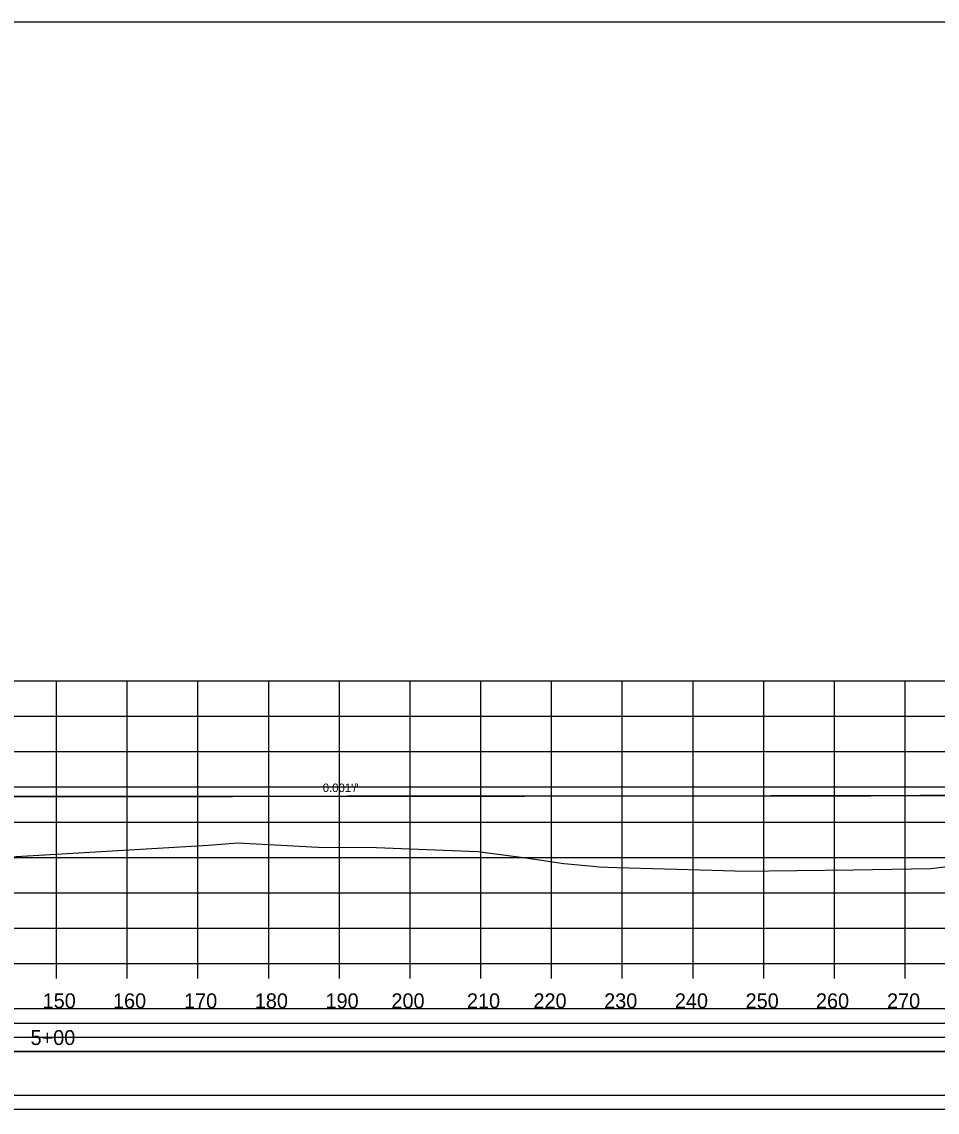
# Model space of a CAD drawing. Extents: x 1370565 to 1374448, y 301010 to 304637.
# Drawn here: x 1374196.6 to 1374326, y 301573 to 301727.1 of the extents above; entities that cross this region are included whole.
import ezdxf

# ---------------------------------------------------------------- set-up
doc = ezdxf.new("R2010")
doc.units = 0
for name, color, linetype in [('Default', 7, 'Continuous'), ('R_Axis', 7, 'Continuous'), ('R_Axis Annot', 7, 'Continuous'), ('R_Border', 7, 'Continuous'), ('R_Contours', 7, 'Continuous'), ('R_Drive', 7, 'Continuous'), ('R_Exist Surface', 7, 'Continuous'), ('R_Fin Surface', 7, 'Continuous'), ('R_Grid', 7, 'Continuous'), ('R_No Plot', 7, 'Continuous'), ('R_Xsect Slope', 7, 'Continuous')]:
    doc.layers.add(name, color=color, linetype=linetype)

msp = doc.modelspace()

# ---------------------------------------------------------------- linework, layer by layer
at = {"layer": 'Default'}
for points in [[(1373981.44, 301583.58), (1374421.61, 301583.58), (1374421.61, 301587.57), (1373981.44, 301587.57)], [(1373981.44, 301575.36), (1374421.61, 301575.36), (1374421.61, 301583.5), (1373981.44, 301583.5)]]:
    msp.add_lwpolyline(points, close=True, dxfattribs=at)
at = {"layer": 'R_Axis'}
for p, q in [((1373981.52, 301593.96), (1374421.52, 301593.96)), ((1374201.52, 301591.86), (1374201.52, 301593.96)), ((1374211.52, 301591.86), (1374211.52, 301593.96)), ((1374221.52, 301591.86), (1374221.52, 301593.96)), ((1374231.52, 301591.86), (1374231.52, 301593.96)), ((1374241.52, 301591.86), (1374241.52, 301593.96)), ((1374251.52, 301591.86), (1374251.52, 301593.96)), ((1374261.52, 301591.86), (1374261.52, 301593.96)), ((1374271.52, 301591.86), (1374271.52, 301593.96)), ((1374281.52, 301591.86), (1374281.52, 301593.96)), ((1374291.52, 301591.86), (1374291.52, 301593.96)), ((1374301.52, 301591.86), (1374301.52, 301593.96)), ((1374311.52, 301591.86), (1374311.52, 301593.96)), ((1374321.52, 301591.86), (1374321.52, 301593.96))]:
    msp.add_line(p, q, dxfattribs=at)
at = {"layer": 'R_Border'}
msp.add_line((1373966.52, 301727.15), (1374440.79, 301727.15), dxfattribs=at)
at = {"layer": 'R_Contours'}
for points in [[(1374357.82, 301617.75), (1374352.3, 301617.75), (1374323.59, 301617.72), (1374316.64, 301617.71), (1374313.43, 301617.71), (1374312.94, 301617.71), (1374308.35, 301617.7), (1374305.89, 301617.7), (1374302.51, 301617.7), (1374267.71, 301617.66), (1374265.43, 301617.66), (1374255.43, 301617.65), (1374255.15, 301617.65), (1374242.59, 301617.64), (1374226.41, 301617.62), (1374217.08, 301617.61), (1374209.87, 301617.61), (1374187.8, 301617.58), (1374183.39, 301617.58), (1374156.91, 301617.55), (1374154.16, 301617.55), (1374151.29, 301617.55), (1374124.9, 301617.52), (1374107.34, 301611.73)], [(1374191.74, 301608.89), (1374223.01, 301610.7), (1374227.12, 301611.04), (1374238.52, 301610.45), (1374246.78, 301610.39), (1374256.22, 301610), (1374261.11, 301609.81), (1374267.86, 301608.94), (1374273.25, 301608.14), (1374277.39, 301607.73), (1374278.22, 301607.65), (1374280.75, 301607.58), (1374294.21, 301607.17), (1374297.43, 301607.07), (1374298.23, 301607.05), (1374314.17, 301607.21), (1374325.12, 301607.44), (1374327.89, 301607.77), (1374332.91, 301608.53), (1374336.14, 301611.18), (1374341.9, 301616.12), (1374352.58, 301617.17), (1374355.93, 301617.57), (1374357.82, 301617.66)]]:
    msp.add_lwpolyline(points, dxfattribs=at)
at = {"layer": 'R_Drive'}
for points in [[(1373981.52, 301581.52), (1374421.73, 301581.52), (1374421.73, 301585.51), (1373981.52, 301585.51)], [(1373981.52, 301573.38), (1374421.73, 301573.38), (1374421.73, 301581.52), (1373981.52, 301581.52)]]:
    msp.add_lwpolyline(points, close=True, dxfattribs=at)
at = {"layer": 'R_Exist Surface'}
msp.add_lwpolyline([(1374191.74, 301608.89), (1374223.01, 301610.7), (1374227.12, 301611.04), (1374238.52, 301610.45), (1374246.78, 301610.39), (1374256.22, 301610), (1374261.11, 301609.81), (1374267.86, 301608.94), (1374273.25, 301608.14), (1374277.39, 301607.73), (1374278.22, 301607.65), (1374280.75, 301607.58), (1374294.21, 301607.17), (1374297.43, 301607.07), (1374298.23, 301607.05), (1374314.17, 301607.21), (1374325.12, 301607.44), (1374327.89, 301607.77)], dxfattribs=at)
at = {"layer": 'R_Fin Surface'}
msp.add_lwpolyline([(1374187.8, 301617.58), (1374209.87, 301617.61), (1374217.08, 301617.61), (1374226.41, 301617.62), (1374242.59, 301617.64), (1374255.15, 301617.65), (1374255.43, 301617.65), (1374265.43, 301617.66), (1374267.71, 301617.66), (1374302.51, 301617.7), (1374305.89, 301617.7), (1374308.35, 301617.7), (1374312.94, 301617.71), (1374313.43, 301617.71), (1374316.64, 301617.71), (1374323.59, 301617.72), (1374352.3, 301617.75), (1374357.82, 301617.75), (1374359.45, 301617.76), (1374359.86, 301617.76)], dxfattribs=at)
at = {"layer": 'R_Grid'}
for p, q in [((1373981.52, 301633.96), (1374421.52, 301633.96)), ((1374201.52, 301593.96), (1374201.52, 301633.96)), ((1374211.52, 301593.96), (1374211.52, 301633.96)), ((1374221.52, 301593.96), (1374221.52, 301633.96)), ((1374231.52, 301593.96), (1374231.52, 301633.96)), ((1374241.52, 301593.96), (1374241.52, 301633.96)), ((1374251.52, 301593.96), (1374251.52, 301633.96)), ((1374261.52, 301593.96), (1374261.52, 301633.96)), ((1374271.52, 301593.96), (1374271.52, 301633.96)), ((1374281.52, 301593.96), (1374281.52, 301633.96)), ((1374291.52, 301593.96), (1374291.52, 301633.96)), ((1374301.52, 301593.96), (1374301.52, 301633.96)), ((1374311.52, 301593.96), (1374311.52, 301633.96)), ((1374321.52, 301593.96), (1374321.52, 301633.96)), ((1373981.52, 301628.96), (1374421.52, 301628.96)), ((1373981.52, 301623.96), (1374421.52, 301623.96)), ((1373981.52, 301618.96), (1374421.52, 301618.96)), ((1373981.52, 301613.96), (1374421.52, 301613.96)), ((1373981.52, 301608.96), (1374421.52, 301608.96)), ((1373981.52, 301603.96), (1374421.52, 301603.96)), ((1373981.52, 301598.96), (1374421.52, 301598.96)), ((1373981.52, 301593.96), (1374421.52, 301593.96))]:
    msp.add_line(p, q, dxfattribs=at)
at = {"layer": 'R_No Plot'}
msp.add_lwpolyline([(1374317.4, 301727.15), (1374346.83, 301727.15), (1374346.83, 301712.33), (1374371, 301712.33), (1374405.8, 301712.33), (1374405.98, 301670.09), (1374440.79, 301670.09), (1374440.79, 301418.96), (1373966.52, 301418.96), (1373966.52, 301727.15)], close=True, dxfattribs=at)

# ---------------------------------------------------------------- texts
at = {"layer": 'R_Axis Annot'}
for s, p in [('150', (1374199.55, 301587.66)), ('160', (1374209.5, 301587.66)), ('170', (1374219.55, 301587.66)), ('180', (1374229.55, 301587.66)), ('190', (1374239.55, 301587.66)), ('200', (1374248.87, 301587.66)), ('210', (1374259.55, 301587.66)), ('220', (1374268.95, 301587.66)), ('230', (1374278.95, 301587.66)), ('240', (1374288.95, 301587.66)), ('250', (1374298.95, 301587.66)), ('260', (1374308.9, 301587.66)), ('270', (1374318.95, 301587.66)), ('5+00', (1374197.84, 301582.46))]:
    msp.add_text(s, height=2.1, dxfattribs=at).set_placement(p)
at = {"layer": 'R_Xsect Slope'}
msp.add_text("0.001'/'", height=1.2, rotation=0.0573, dxfattribs=at).set_placement((1374239.16, 301618.23))

doc.saveas('drawing.dxf')
